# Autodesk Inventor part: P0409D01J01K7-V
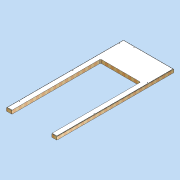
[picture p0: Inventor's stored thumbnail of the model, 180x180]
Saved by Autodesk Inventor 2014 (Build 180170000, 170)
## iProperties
Created: 2011-04
Part Number: P0409D01J01K7-V
Document SubType Name: Modeling
Designer: david.appleford
Density: 0.371936 g/cm^3
Description: 1w x 2w  01 Door Panel - 7 Locks
Cost Center: £143.00
Mass: 36000 g
Surface Area: 33776.2 cm^2
Volume: 96790.8 cm^3
Material: Generic
Appearance: Wood (Pine)
Justset: False
Title: 1w x 2w  01 Panel - 6 Locks
Author: david.appleford
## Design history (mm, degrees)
sketch "Sketch1"
  geometry: L1 (0, 0)-(1220, 0); L2 (1220, 0)-(1220, 2745); L3 (1220, 2745)-(0, 2745); L4 (0, 2745)-(0, 0); L5 (34, 2711)-(1186, 2711); L6 (1186, 2711)-(1186, 34); L7 (1186, 34)-(34, 34); L8 (34, 34)-(34, 2711)
  constraints: 16 end point, 4 parallel, 2 perpendicular, 1 horizontal, 3 other
  dimensions: "d0" = 1220 distance between parallel lines of L2 L4 (= w); "d1" = 2745 distance between parallel lines of L1 L3 (= 2.25 x w); "d2" = 34 distance between parallel lines of L5 L3 (= 0.5 x t); "d29" = 2677 distance between parallel lines of L7 L5 (derived); "d30" = 1152 distance between parallel lines of L6 L8 (derived)
extrude "Extrusion1" new body sketch "Sketch1" distance "d3" = 68 (= t); taper "d4" = 0 deg
sketch "Sketch2"
  geometry: L1 (1186, 2711)-(1186, 34) reference; L2 (34, 2711)-(1186, 2711) reference; L3 (34, 34)-(34, 2711) reference; L4 (1186, 34)-(34, 34) reference; L5 (1176, 2701)-(1176, 44); L6 (1176, 44)-(44, 44); L7 (44, 44)-(44, 2701); L8 (44, 2701)-(1176, 2701); 1 further point
  constraints: 8 end point, 3 other
  dimensions: "d5" = 10 distance between parallel lines of L8 L2
extrude "Extrusion2" join sketch "Sketch2" distance "d6" = 6 (= sw); taper "d7" = 0 deg
sketch "Sketch3"
  geometry: L1 (-44, 2701)-(-1176, 2701) reference; L2 (-1176, 2701)-(-1176, 44) reference; L3 (-44, 44)-(-44, 2701) reference; L4 (-1176, 44)-(-44, 44) reference; 1 further point
extrude "Extrusion3" join sketch "Sketch3" distance "d8" = 6 (= sw); taper "d9" = 0 deg
sketch "Sketch4"
  geometry: L1 (34, 2711)-(1186, 2711) reference; L2 (1186, 2711)-(1186, 34) reference; L3 (1186, 34)-(34, 34) reference; L4 (34, 34)-(34, 2711) reference; 8 further points
  constraints: 3 vertical alignment
  dimensions: "d10" = 28 distance from line of point (305, 2683) L1 (= k); "d12" = 28 distance from line of L3 point (915, 62) (= k); "d13" = 28 distance from line of point (62, 305) L4 (= k); "d14" = 305 horizontal distance of point (305, 2683) point (0, 0) (= 0.25 x w); "d15" = 610 horizontal distance of point (915, 62) point (305, 2683) (= 0.5 x w); "d16" = 305 vertical distance of point (62, 305) point (0, 0) (= 0.25 x w); "d17" = 1220 distance of point (62, 305) point (62, 1525) (= w); "d19" = 610 vertical distance of point (1158, 915) point (62, 305) (= 0.5 x w); "d20" = 1220 distance of point (1158, 915) point (1158, 2135) (= w); "d31" = 1067.5 distance of point (62, 1525) point (62, 2592.5)
hole "Hole1" sketch "Sketch4" at (305, 2683), (62, 1525), (62, 305), (1158, 2135), (1158, 915), (915, 62), (62, 2592.5) diameter "d22" = 12 (= hd); stored, may be unused: countersink angle "d26" = 90 deg, drill point angle "d28" = 118 deg; dims "d23" = 6, "d24" = 4, "d25" = 2, "d27" = 8
sketch "Sketch5"
  geometry: L1 (172, 2069)-(1048, 2069); L2 (1068, 2049)-(1068, 34); L3 (1068, 34)-(152, 34); L4 (152, 34)-(152, 2049); L5 (1186, 34)-(34, 34) reference; L6 (34, 34)-(34, 2711) reference; L7 (1186, 2711)-(1186, 34) reference; A1 r 20 centre (172, 2049) between (172, 2069) and (152, 2049); A2 r 20 centre (1048, 2049) between (1068, 2049) and (1048, 2069); 1 further point
  constraints: 8 end point, 4 point on circle, 4 tangent, 2 centre point, 1 collinear, 1 equal radius
  dimensions: "d32" = 916 distance between parallel lines of L2 L4; "d33" = 2035 distance between parallel lines of L3 L1; "d34" = 118 distance between parallel lines of L6 L4 (= -0.5 x d32 + 0.5 x d35); "d35" = 1152 distance between parallel lines of L7 L6 (derived); "d36" = 20 radius of A1
extrude "Extrusion4" cut sketch "Sketch5" stored distance "d37" = 10; taper "d38" = 0 deg
body "Solid1"
node "Projected Loop1"
other parameters: "w" = 1220 [user parameter; used in 8 equation terms], "t" = 68 [user parameter; used in 2 equation terms], "e" = 16 [user parameter], "sw" = 6 [user parameter; used in 2 equation terms], "sc" = 9 [user parameter], "sf" = 12 [user parameter], "k" = 28 [user parameter; used in 3 equation terms], "hd" = 12 [user parameter; used in 1 equation term]
